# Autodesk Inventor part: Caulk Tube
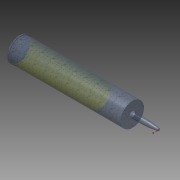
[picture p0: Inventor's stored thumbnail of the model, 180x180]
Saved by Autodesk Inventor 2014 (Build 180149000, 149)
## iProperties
Created: 2009-03
Part Number: Caulk Tube
Document SubType Name: Modeling
Designer: tangg
Density: 3.18 g/cm^3
Material: Silicon Nitride
Mass: 657.694 g
Surface Area: 779.569 cm^2
Volume: 206.822 cm^3
Appearance: Water Bubbles
Author: tangg
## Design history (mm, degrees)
sketch "Sketch1"
  geometry: L1 (0.01, 26.745)-(-252.99, 26.745); L2 (-255.99, 26.745)-(-255.99, 0.245); L3 (-255.99, 0.245)-(0.01, 0.245); L4 (0.01, 0.245)-(0.01, 26.745); L5 (0.01, 0.245)-(60.01, 0.245); L6 (60.01, 0.245)-(60.01, 2.745); L7 (-252.99, 26.745)-(-252.99, 27.799); L8 (-252.99, 27.799)-(-255.99, 27.799); L9 (-255.99, 27.799)-(-255.99, 26.745); 4 further points
  constraints: 18 end point, 3 parallel, 3 perpendicular, 1 horizontal, 1 point on line, 4 other
  dimensions: "d25" = 26.5 distance between parallel lines of L3 L1; "d26" = 256 distance between parallel lines of L2 L4; "d27" = 60 distance between parallel lines of L4 L6; "d28" = 32 distance from line of L4 point (32.01, 6.016); "d29" = 6.5 distance of point (0, 0) point (0.01, 6.5); "d30" = 2.5 distance of L5.end L6.end; "d33" = 3 distance between parallel lines of L9 L7
revolve "Revolution1" sketch "Sketch1" stored, may be unused: angle "d17" = 90 deg
sketch "Sketch2"
  geometry: C1 r 26.5 at (0, 0); C2 r 25.5 at (0, 0); 1 further point
  constraints: 2 centre point, 1 concentric
  dimensions: "d18" = 1 radial gap between concentric circles of C2 C1
extrude "Extrusion1" cut sketch "Sketch2" distance "d19" = 182; taper "d20" = 0 deg
sketch "Sketch3"
  geometry: L1 (60.161, 0)-(60.161, -7.769); 4 further points
  constraints: 2 end point, 1 vertical, 5 other
revolve "Revolution2" sketch "Sketch3" stored, may be unused: angle "d31" = 90 deg
sketch "Sketch4"
  geometry: L1 (59.994, -10.28)-(59.994, -13.757); 3 further points
  constraints: 2 end point, 1 vertical, 4 other
revolve "Revolution3" sketch "Sketch4" stored, may be unused: angle "d32" = 90 deg
body "Solid1"
